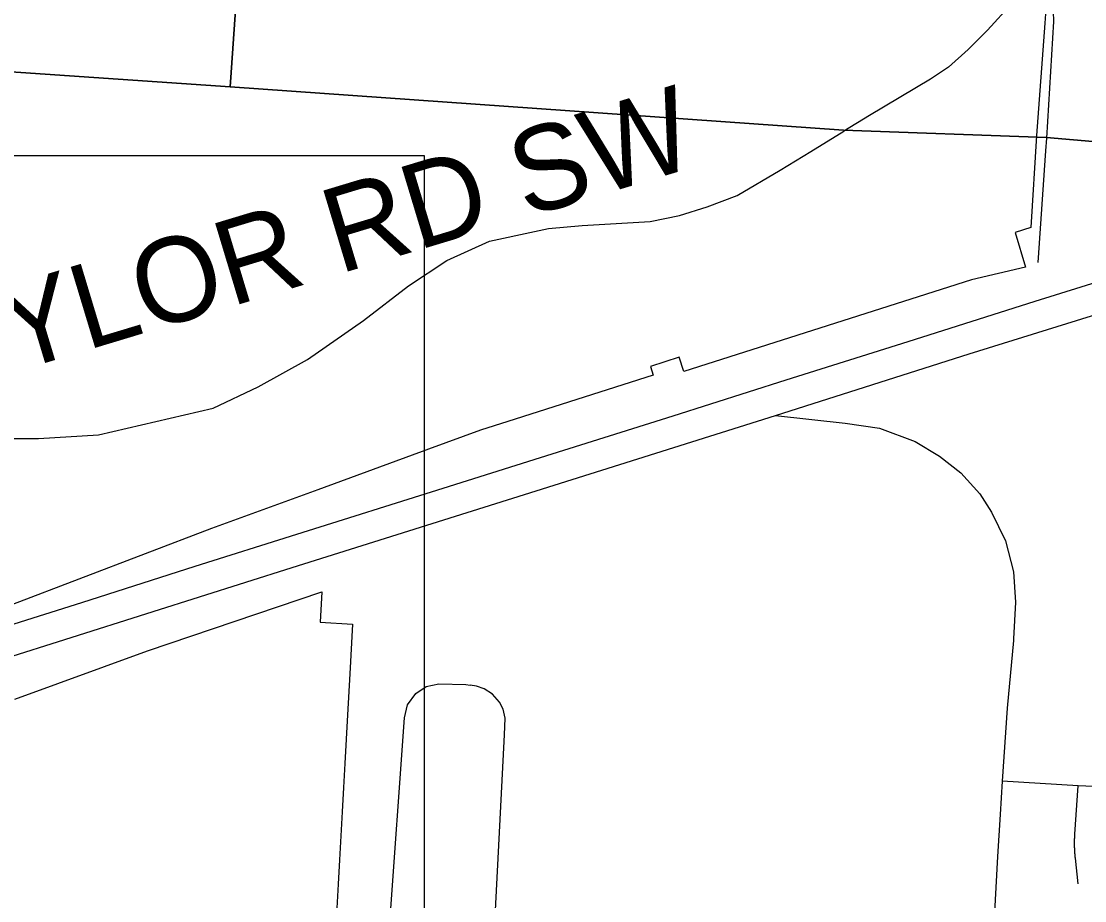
# Model space of a CAD drawing. Extents: x 1880545 to 1948545, y 79309 to 723051.
# Drawn here: x 1888580 to 1892101, y 703927 to 706837 of the extents above; entities that cross this region are included whole.
import ezdxf

# ---------------------------------------------------------------- set-up
doc = ezdxf.new("R2010")
doc.units = 0
for name, color, linetype in [('GM_X_Corporation', 7, 'Continuous'), ('GM_X_County', 7, 'Continuous'), ('GM_X_County_Road', 7, 'Continuous'), ('GM_X_Interstate_Route', 7, 'Continuous'), ('GM_X_State_Route', 7, 'Continuous'), ('GM_X_Township', 7, 'Continuous'), ('GM_X_Township_Road', 7, 'Continuous'), ('SH_Text', 7, 'Continuous')]:
    doc.layers.add(name, color=color, linetype=linetype)

msp = doc.modelspace()

# ---------------------------------------------------------------- linework, layer by layer
at = {"layer": 'GM_X_Corporation'}
for points in [[(1891970.5, 706861.5), (1891968.6, 706830.1), (1891940.8, 706458.7), (1891921.7, 706154), (1891870.1, 706137.5), (1891904.6, 706022.8), (1891725.6, 705981.3), (1890773.1, 705677.4), (1890758, 705725.1), (1890662.7, 705694.6), (1890671.9, 705666.1), (1890190.7, 705512.6), (1890100.4, 705483.8), (1889928.2, 705420.8), (1889561.9, 705286.6), (1889210.1, 705157.8), (1888551.1, 704906.4)], [(1888558.6, 704593.4), (1888998.2, 704753.1), (1889575.1, 704948.2), (1889569.6, 704848.4), (1889676.5, 704841.2), (1889667.6, 704677.8), (1889660.1, 704542.2), (1889655.7, 704460.8), (1889651.4, 704380.9), (1889647, 704301), (1889642.6, 704221.1), (1889638.2, 704141.2), (1889633.9, 704061.3), (1889629.5, 703981.5), (1889624, 703881.6)]]:
    msp.add_lwpolyline(points, dxfattribs=at)
at = {"layer": 'GM_X_County'}
for points in [[(1891843, 720211.7), (1891817.3, 719823), (1890199.9, 719967.4), (1890149.5, 719242.8), (1889939.7, 716226.1), (1889896.4, 715603.5), (1889789, 714059.4), (1889788.8, 714056.5), (1889727.7, 713178.3), (1889727.7, 713177.2), (1889679.5, 712484.9), (1889676.5, 712442.3), (1889513.2, 710094.6), (1889456, 709272.2), (1889271.5, 706620), (1886740.8, 706792.8), (1884485.1, 706946.7)], [(1889271.5, 706620), (1891302.3, 706476.1), (1891973.7, 706452.7), (1893110.2, 706354.4), (1893306.8, 706337.4), (1894183.2, 706296.7), (1895332.2, 706215.1), (1898402.8, 705973), (1899946.7, 705888.4), (1900524.2, 705848.3), (1900987.7, 705813.2), (1901285.2, 705793.5), (1903803.3, 705612.3), (1907401, 705337.3), (1908909.6, 705222.3), (1910547.6, 705097.3), (1912287.5, 704989.5), (1913212.7, 704930.7), (1917682.9, 704647.7), (1918575.4, 704595.6), (1920101.7, 704497.5), (1921284.7, 704420.1), (1922414.3, 704343.6)]]:
    msp.add_lwpolyline(points, dxfattribs=at)
at = {"layer": 'GM_X_County_Road'}
msp.add_lwpolyline([(1888463.8, 705455.7), (1888637.4, 705455.7), (1888835.5, 705468), (1889215.4, 705556.3), (1889363.9, 705626.9), (1889528.2, 705717.8), (1889712.7, 705846.1), (1889862.6, 705961.5), (1889989.4, 706045.1), (1890130.1, 706109), (1890278.7, 706141.5), (1890325, 706151.1), (1890436.4, 706160.6), (1890662.1, 706174.1), (1890759.5, 706193.7), (1890851.1, 706222.9), (1890950.5, 706259.9), (1891092.8, 706343.8), (1891194.2, 706406.2), (1891303.5, 706473.3)], dxfattribs=at)
at = {"layer": 'GM_X_Interstate_Route'}
for points in [[(1888310.7, 704765.3), (1888780.9, 704913.6), (1889155.3, 705033.4), (1889492.7, 705139.1), (1889977, 705291.4), (1890298.9, 705392.8), (1890737.7, 705531), (1891112.1, 705649.8), (1891515.7, 705776.7), (1891936.2, 705910.1), (1892241.1, 706005.5), (1892474.6, 706082.1), (1892683.2, 706160.5), (1892864, 706236.2), (1893111.4, 706351.5)], [(1891076.9, 705531.7), (1891718.6, 705735.8), (1892155.1, 705872.5), (1892470.3, 705975.4), (1892693.5, 706056.2), (1892904, 706143.1), (1893057.1, 706211.3), (1893308, 706334.5)], [(1888523.9, 704727.2), (1888528.9, 704728.8), (1888724.1, 704790.7), (1889016.7, 704883.6), (1889477.2, 705029.7), (1889978.9, 705187.5), (1890284.8, 705282.9), (1891076.9, 705531.7)]]:
    msp.add_lwpolyline(points, dxfattribs=at)
at = {"layer": 'GM_X_State_Route'}
for points in [[(1891076.9, 705531.7), (1891307.1, 705507.2), (1891421.7, 705490.3), (1891539.2, 705446.2), (1891619.5, 705397.8), (1891690, 705342.8), (1891752.9, 705273.3), (1891792.4, 705212.7), (1891838, 705117.8), (1891864.4, 705015.4), (1891870.9, 704914.8), (1891865, 704792.8)], [(1891865, 704792.8), (1891864.7, 704787.5), (1891844.1, 704563.9), (1891827.6, 704322.4), (1891820.7, 704211.5)], [(1891820.7, 704211.5), (1891812.1, 704072.9), (1891777.4, 703436.6)]]:
    msp.add_lwpolyline(points, dxfattribs=at)
at = {"layer": 'GM_X_Township'}
for points in [[(1886104.1, 720211.7), (1886445.3, 720189.4), (1890199.9, 719967.4), (1890149.5, 719242.8), (1889939.7, 716226.1), (1889896.4, 715603.5), (1889789, 714059.4), (1889788.8, 714056.5), (1889727.7, 713178.3), (1889727.7, 713177.2), (1889679.5, 712484.9), (1889676.5, 712442.3), (1889513.2, 710094.6), (1889456, 709272.2), (1889271.5, 706620), (1886740.8, 706792.8), (1884485.1, 706946.7)], [(1922414.3, 704343.6), (1921284.7, 704420.1), (1920101.7, 704497.5), (1918575.4, 704595.6), (1917682.9, 704647.7), (1913212.7, 704930.7), (1912287.5, 704989.5), (1910547.6, 705097.3), (1908909.6, 705222.3), (1907401, 705337.3), (1903803.3, 705612.3), (1901285.2, 705793.5), (1900987.7, 705813.2), (1900524.2, 705848.3), (1899946.7, 705888.4), (1898402.8, 705973), (1895332.2, 706215.1), (1894183.2, 706296.7), (1893306.8, 706337.4), (1893110.2, 706354.4), (1891973.7, 706452.7), (1891302.3, 706476.1), (1889271.5, 706620), (1889456, 709272.2)], [(1884485.1, 706946.7), (1886740.8, 706792.8), (1889271.5, 706620), (1891302.3, 706476.1), (1891973.7, 706452.7), (1893110.2, 706354.4), (1893306.8, 706337.4), (1894183.2, 706296.7), (1895332.2, 706215.1), (1898402.8, 705973), (1899946.7, 705888.4), (1900524.2, 705848.3), (1900987.7, 705813.2), (1901285.2, 705793.5), (1903803.3, 705612.3)]]:
    msp.add_lwpolyline(points, dxfattribs=at)
at = {"layer": 'GM_X_Township_Road'}
for points in [[(1891971.2, 707078.6), (1891958.1, 707049.5), (1891919.2, 706983.5), (1891899.7, 706952.9), (1891859.4, 706896), (1891779.2, 706807), (1891714.9, 706743.2), (1891649.5, 706685.5), (1891589.7, 706645.6), (1891387.8, 706525), (1891303.5, 706473.3)], [(1891974.9, 706449.9), (1891997.9, 706835.7), (1891997.6, 706869.6), (1891993.5, 706900.2), (1891989.6, 706909.5)], [(1891946.6, 706039), (1891972, 706407.8), (1891974.9, 706449.9)], [(1889794.4, 702905.5), (1889772.5, 702987.7), (1889762.1, 703038.8), (1889760.5, 703085.3), (1889764.7, 703173.1), (1889799.2, 703838.9), (1889849.1, 704531.4), (1889859.1, 704574.6), (1889886.1, 704611.9), (1889921, 704635.3), (1889963, 704644.3), (1890051.3, 704642.4), (1890066.6, 704640.1)], [(1889764.7, 703173.1), (1889883.8, 703172.5), (1889954.8, 703186.7), (1890025.3, 703207.6), (1890064.5, 703230.5), (1890092.7, 703261.3), (1890114.1, 703307.3), (1890119.8, 703359), (1890134.4, 703594.6), (1890179.6, 704476), (1890181.7, 704530.8), (1890175.7, 704560.2), (1890163.1, 704583.6), (1890140.2, 704610.1), (1890112, 704627.5), (1890086.9, 704636.1), (1890066.6, 704640.1)], [(1892155.7, 704303), (1892078.7, 704306.6), (1891827.6, 704322.4)], [(1892079.1, 703982.7), (1892069.7, 704066.9), (1892069.3, 704071), (1892068.9, 704075), (1892068.6, 704079), (1892068.3, 704083), (1892068, 704087), (1892067.7, 704090.9), (1892067.5, 704095), (1892067.3, 704099), (1892067.2, 704103), (1892067.1, 704107), (1892067, 704111), (1892067, 704115), (1892067, 704118.9), (1892067, 704122.9), (1892067.1, 704126.9), (1892067.2, 704130.9), (1892067.3, 704134.9), (1892067.5, 704138.9), (1892067.7, 704142.9), (1892068, 704146.9), (1892078.7, 704306.6)]]:
    msp.add_lwpolyline(points, dxfattribs=at)
at = {"layer": 'SH_Text'}
msp.add_lwpolyline([(1885062.7, 706393), (1889914.4, 706393), (1889914.4, 701943.1), (1885062.7, 701943.1)], close=True, dxfattribs=at)

# ---------------------------------------------------------------- texts
msp.add_text('TAYLOR RD SW', height=279.999, rotation=16.8035, dxfattribs=at).set_placement((1888098.3, 705536.6))

doc.saveas('drawing.dxf')
